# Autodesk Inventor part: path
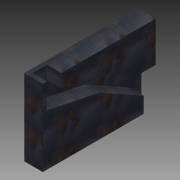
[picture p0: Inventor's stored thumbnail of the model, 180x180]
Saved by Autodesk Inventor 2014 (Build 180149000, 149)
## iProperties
Created: 2005-08
Part Number: path
Document SubType Name: Modeling
Designer: henderh
Density: 1 g/cm^3
Mass: 1427.3 g
Surface Area: 1337.19 cm^2
Volume: 1427.3 cm^3
Material: Generic
Appearance: Metal-Steel (Oxidized)
Author: henderh
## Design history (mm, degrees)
sketch "Sketch1"
  geometry: L1 (69.85, 187.313)-(69.85, 168.287) reference; L2 (307.975, 407.933)-(307.975, 392.058) reference; L3 (265.113, 166.633)-(95.25, 166.633); L4 (95.25, 166.633)-(95.25, 417.458); L5 (95.25, 417.458)-(265.112, 417.458); L6 (265.112, 417.458)-(265.113, 166.633); L7 (280.987, -217.542)-(280.987, 417.458) reference
  constraints: 8 end point, 2 parallel, 1 horizontal, 1 perpendicular, 1 point on line
  dimensions: "d0" = 15.875 distance between parallel lines of L7 L6; "d1" = 25.4 distance between parallel lines of L4 L1; "d2" = 250.825 distance of L3.end L4.end
extrude "Extrusion1" new body sketch "Sketch1" distance "d3" = 50.8; taper "d4" = 0 deg
sketch "Sketch2"
  geometry: L1 (9.525, 9.525)-(41.275, 9.525); L2 (41.275, 9.525)-(41.275, 41.275); L3 (41.275, 41.275)-(9.525, 41.275); L4 (9.525, 41.275)-(9.525, 9.525); A1 r 15.875 centre (25.4, 25.4) between (9.525, 25.4) and (41.275, 25.4) reference
  constraints: 8 end point, 2 midpoint, 2 parallel, 1 horizontal, 1 perpendicular, 1 tangent
  node "Reference4"
sketch "Sketch3"
  geometry: L1 (50.8, 0)-(50.8, 250.825) reference; L2 (0, 250.825)-(50.8, 250.825) reference; L3 (0, 0)-(0, 250.825) reference; C1 r 9.513 at (25.4, 11.167) reference
  node "Reference5"
sketch "3D Sketch1" dims "d6" = 42.93288 (derived), "d8" = 123.71335 (derived), "d9" = 44.29657 (derived), "d10" = 17.74748 (derived)
sweep "Sweep1" sketch "3D Sketch1" dims "d11" = 0
sketch "Sketch4"
  geometry: L1 (-166.633, 95.25)-(-417.458, 95.25) reference; L2 (-166.633, 265.113)-(-166.633, 95.25) reference; L3 (-417.458, 265.112)-(-166.633, 265.113) reference; L4 (-417.458, 95.25)-(-417.458, 265.112) reference
extrude "Extrusion2" cut sketch "Sketch4" stored distance "d12" = 38.1; taper "d13" = 0 deg
sketch "Sketch5"
  geometry: L1 (0, 0)-(-113.378, 63.736) reference; L2 (0, 113.632)-(0, 0) reference; L3 (-209.55, 113.632)-(0, 113.632) reference; L4 (-209.55, 113.632)-(-209.55, 83.627) reference; L5 (0, 24.732)-(-43.995, 24.732)
  constraints: 2 end point, 2 point on line, 1 parallel, 1 perpendicular
  dimensions: "d14" = 88.9 distance between parallel lines of L5 L3
extrude "Extrusion3" cut sketch "Sketch5" stored distance "d15" = 38.1; taper "d16" = 0 deg
body "Solid1"
node "Reference1"
node "Reference2"
node "Reference3"
